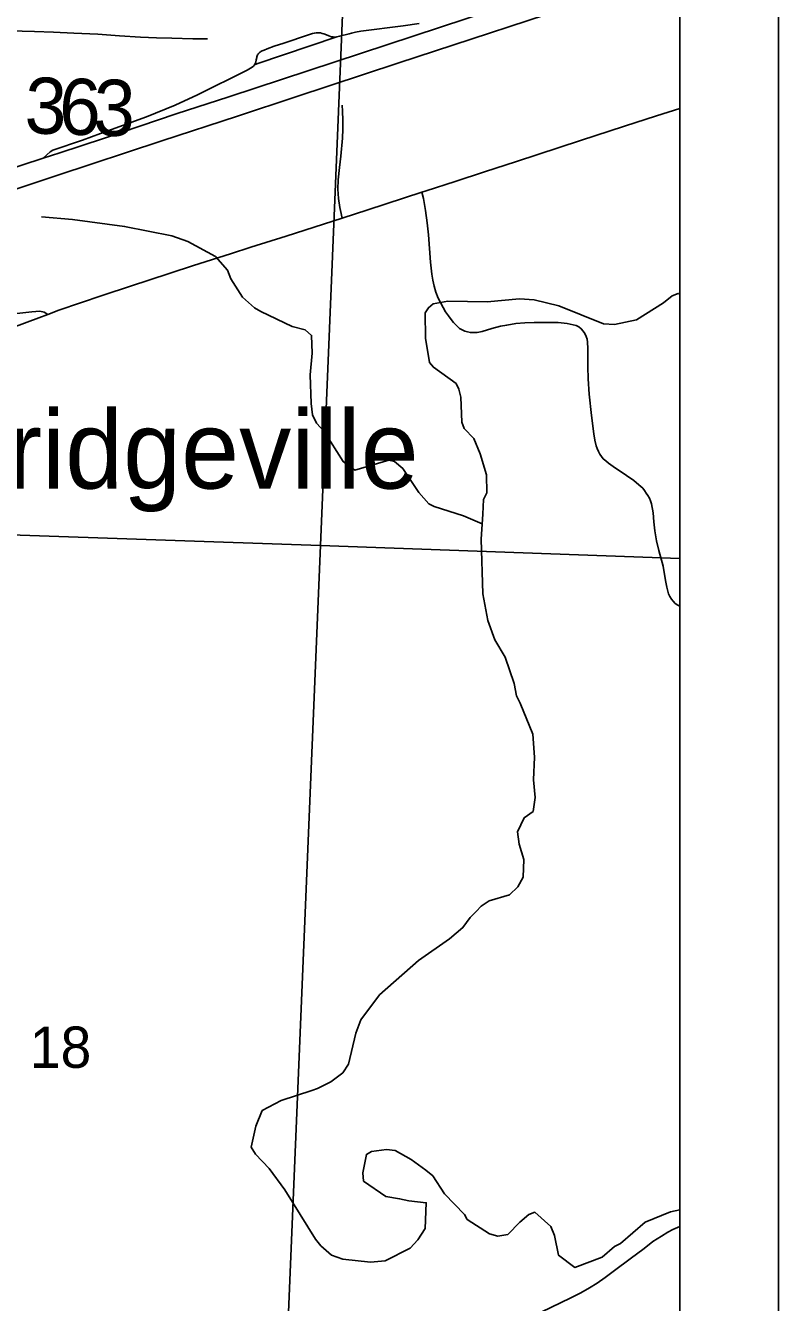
# Model space of a CAD drawing. Extents: x 0 to 34, y 0 to 22.
# Drawn here: x 8.237 to 9, y 16.42 to 17.712 of the extents above; entities that cross this region are included whole.
import ezdxf

# ---------------------------------------------------------------- set-up
doc = ezdxf.new("R2010")
doc.units = 0
for name, color, linetype in [('GM_X_Interchange_Ramps', 7, 'Continuous'), ('GM_X_Interstate_Route', 7, 'Continuous'), ('GM_X_Minor_River', 7, 'Continuous'), ('GM_X_Rail_Line', 7, 'Continuous'), ('GM_X_Section', 7, 'Continuous'), ('GM_X_Section_Text', 7, 'Continuous'), ('GM_X_Township_Road', 7, 'Continuous'), ('GM_X_Township_Road_Text', 7, 'Continuous'), ('GM_X_Unincorporated_Text', 7, 'Continuous'), ('GM_X_US_Route', 7, 'Continuous'), ('SH_Data', 7, 'Continuous')]:
    doc.layers.add(name, color=color, linetype=linetype)

msp = doc.modelspace()

# ---------------------------------------------------------------- linework, layer by layer
at = {"layer": 'GM_X_Interchange_Ramps'}
for points in [[(8.6362, 17.7146), (8.62, 17.7122), (8.5769, 17.7067), (8.5714, 17.7057), (8.5676, 17.7048), (8.5651, 17.7041), (8.5555, 17.7015), (8.5525, 17.7009), (8.5494, 17.7008), (8.5485, 17.7009), (8.5474, 17.701), (8.5464, 17.7013), (8.5447, 17.702), (8.5423, 17.703), (8.5395, 17.704), (8.5379, 17.7045), (8.5362, 17.7049), (8.5347, 17.7051), (8.5338, 17.7052), (8.533, 17.7052), (8.5316, 17.705), (8.5298, 17.7046), (8.5279, 17.7042), (8.5241, 17.7031), (8.499, 17.6946), (8.4891, 17.6914), (8.482, 17.6888), (8.479, 17.6876), (8.4771, 17.6868), (8.4756, 17.686), (8.475, 17.6856), (8.4744, 17.6852), (8.4739, 17.6848), (8.4733, 17.6842), (8.4728, 17.6835), (8.4723, 17.6826), (8.472, 17.6819), (8.4717, 17.6809), (8.4715, 17.6799), (8.4711, 17.6777), (8.4706, 17.6754), (8.47, 17.6739), (8.4692, 17.6726), (8.4681, 17.6714), (8.467, 17.6704), (8.4653, 17.6693), (8.4617, 17.6671), (8.4115, 17.6423), (8.3888, 17.6318), (8.36, 17.6201), (8.3131, 17.603), (8.2949, 17.5965), (8.265, 17.5861), (8.2623, 17.5845), (8.2553, 17.5781)], [(8.5525, 17.7009), (8.4716, 17.6738), (8.4692, 17.6726)]]:
    msp.add_lwpolyline(points, dxfattribs=at)
at = {"layer": 'GM_X_Interstate_Route'}
for points in [[(8.1512, 17.5213), (8.2691, 17.5606), (8.3753, 17.5956), (8.4521, 17.6208), (8.5111, 17.6402), (8.6143, 17.6743), (8.8209, 17.742)], [(7.2772, 17.4256), (7.4507, 17.4388), (7.6458, 17.4538), (7.7914, 17.465), (7.8502, 17.4696), (7.8812, 17.4725), (7.9059, 17.4755), (7.9274, 17.4788), (7.9488, 17.4827), (7.9701, 17.4873), (7.9912, 17.4927), (8.0152, 17.4996), (8.0507, 17.5108), (8.0653, 17.5156), (8.213, 17.5644), (8.2553, 17.5781), (8.2721, 17.5836), (8.3164, 17.5982), (8.39, 17.6229), (8.4432, 17.6401), (8.711, 17.7284)]]:
    msp.add_lwpolyline(points, dxfattribs=at)
at = {"layer": 'GM_X_Minor_River'}
for points in [[(8.6999, 17.2078), (8.6809, 17.216), (8.6513, 17.2253), (8.646, 17.2283), (8.6357, 17.2397), (8.6196, 17.2638), (8.6109, 17.271), (8.6052, 17.2725), (8.5708, 17.2624), (8.559, 17.271), (8.5398, 17.3013), (8.5322, 17.3099), (8.528, 17.3183), (8.5268, 17.3296), (8.5258, 17.3588), (8.5276, 17.3808), (8.5271, 17.3987), (8.5206, 17.4043), (8.5073, 17.4076), (8.4758, 17.423), (8.4693, 17.4267), (8.4571, 17.4373), (8.4453, 17.4558), (8.4418, 17.4649), (8.4296, 17.4785), (8.4018, 17.4938), (8.3855, 17.4994), (8.3377, 17.509), (8.285, 17.5159), (8.2536, 17.5187)], [(8.9, 17.4403), (8.8984, 17.4412), (8.8923, 17.4389), (8.8837, 17.4316), (8.8561, 17.4144), (8.8338, 17.4097), (8.8228, 17.4104), (8.7776, 17.4287), (8.7526, 17.4346), (8.7378, 17.4356), (8.7049, 17.4328), (8.6651, 17.4333), (8.6503, 17.4305), (8.6454, 17.4267), (8.6421, 17.4214), (8.6426, 17.396), (8.6466, 17.3713), (8.6504, 17.3664), (8.6736, 17.3499), (8.6763, 17.3442), (8.6782, 17.3363), (8.6792, 17.3109), (8.6815, 17.3044), (8.6914, 17.2942), (8.6979, 17.2787), (8.7041, 17.2575), (8.7046, 17.2393), (8.7013, 17.2325), (8.7006, 17.2177), (8.6989, 17.1923), (8.7004, 17.1369), (8.7055, 17.11), (8.7128, 17.0903), (8.7232, 17.0729), (8.7324, 17.0464), (8.7348, 17.0339), (8.7383, 17.0264)], [(8.7383, 17.0264), (8.7513, 16.995), (8.753, 16.9718), (8.752, 16.9487), (8.7537, 16.9309), (8.7515, 16.9168), (8.7424, 16.9103), (8.7357, 16.8962), (8.7373, 16.8837), (8.742, 16.8682), (8.7413, 16.85), (8.7361, 16.8405), (8.7274, 16.8324), (8.707, 16.8263), (8.6987, 16.8209), (8.6938, 16.8155), (8.6878, 16.8094), (8.6803, 16.7992), (8.6667, 16.7877), (8.6355, 16.7659), (8.5959, 16.7311), (8.5768, 16.7056), (8.5719, 16.6923), (8.5646, 16.6607), (8.5586, 16.652), (8.5465, 16.6428), (8.5329, 16.6362), (8.5272, 16.6343), (8.4963, 16.6239), (8.477, 16.6139), (8.4707, 16.5979), (8.4659, 16.5767), (8.4701, 16.5698), (8.4842, 16.5551), (8.4999, 16.5336), (8.5309, 16.4837), (8.5363, 16.4769), (8.5473, 16.4675), (8.5587, 16.4634), (8.5867, 16.4602), (8.6015, 16.4618), (8.6268, 16.4745), (8.6347, 16.4829), (8.6422, 16.4943), (8.6432, 16.5205), (8.6257, 16.5226), (8.6162, 16.5245), (8.6022, 16.527), (8.5798, 16.5425), (8.5789, 16.5508), (8.5826, 16.5694), (8.5879, 16.5725), (8.603, 16.5745), (8.6117, 16.5734), (8.6281, 16.5644), (8.6429, 16.5535), (8.6498, 16.5478), (8.6617, 16.5297), (8.6819, 16.5086), (8.6846, 16.5037), (8.7074, 16.489), (8.7157, 16.4868), (8.7259, 16.4884), (8.738, 16.501), (8.747, 16.5086), (8.7531, 16.5109), (8.7694, 16.4966), (8.7733, 16.4872), (8.7772, 16.4674), (8.7936, 16.455), (8.8215, 16.4654), (8.834, 16.4761), (8.84, 16.4792), (8.8649, 16.501), (8.8905, 16.5114), (8.9, 16.5133)]]:
    msp.add_lwpolyline(points, dxfattribs=at)
at = {"layer": 'GM_X_Rail_Line'}
msp.add_lwpolyline([(6.4764, 15.22), (8.4272, 15.1429), (8.9, 15.1329), (8.9, 20.2439), (7.9141, 20.2806), (7.3096, 20.3035), (6.6357, 20.3306)], dxfattribs=at)
at = {"layer": 'GM_X_Section'}
for points in [[(7.5782, 18.246), (8.5787, 18.2117), (8.5361, 17.186), (8.0548, 17.2024), (8.0736, 17.7137), (7.5651, 17.7332)], [(8.0548, 17.2024), (8.5361, 17.186), (8.4938, 16.1751), (8.0113, 16.1881)]]:
    msp.add_lwpolyline(points, close=True, dxfattribs=at)
at = {"layer": 'GM_X_Township_Road'}
for points in [[(8.0762, 17.7113), (8.0799, 17.7118), (8.0848, 17.712), (8.0988, 17.7118), (8.1212, 17.7112), (8.1425, 17.7105), (8.1658, 17.7095), (8.1841, 17.7087), (8.1969, 17.708), (8.2154, 17.7073), (8.234, 17.7067), (8.2463, 17.7063), (8.2658, 17.7057), (8.2864, 17.7047), (8.3106, 17.7036), (8.3324, 17.7021), (8.3538, 17.7008), (8.3699, 17.7001), (8.3856, 17.6998), (8.4067, 17.6991), (8.4217, 17.6989)], [(8.5582, 17.5175), (8.5565, 17.5252), (8.5558, 17.5282), (8.5545, 17.5373), (8.5537, 17.5468), (8.5541, 17.5563), (8.5553, 17.5687), (8.5567, 17.5801), (8.5583, 17.5984), (8.5586, 17.6075), (8.5588, 17.6167), (8.5583, 17.6258), (8.558, 17.6319)], [(8.9, 17.1245), (8.898, 17.1256), (8.8955, 17.1273), (8.8932, 17.1295), (8.8915, 17.1317), (8.8901, 17.1343), (8.8887, 17.1371), (8.887, 17.1437), (8.8857, 17.1505), (8.8832, 17.1652), (8.8788, 17.181), (8.8765, 17.1908), (8.8749, 17.2008), (8.8738, 17.2099), (8.8731, 17.2192), (8.8715, 17.2283), (8.8705, 17.2311), (8.8692, 17.2339), (8.8677, 17.2366), (8.866, 17.2391), (8.8644, 17.2415), (8.8625, 17.2439), (8.8585, 17.2475), (8.8536, 17.2518), (8.8461, 17.2569), (8.8324, 17.266), (8.8278, 17.2694), (8.825, 17.2717), (8.8225, 17.2738), (8.8208, 17.276), (8.8191, 17.2785), (8.8176, 17.2813), (8.8163, 17.2841), (8.8152, 17.287), (8.8139, 17.2926), (8.8131, 17.299), (8.8106, 17.3175), (8.8084, 17.3392), (8.8074, 17.3546), (8.8068, 17.367), (8.8068, 17.3855), (8.8066, 17.3917), (8.8061, 17.3948), (8.8053, 17.3977), (8.804, 17.4005), (8.8023, 17.4031), (8.8002, 17.4054), (8.7978, 17.4073), (8.795, 17.4086), (8.792, 17.4094), (8.786, 17.4107), (8.78, 17.4115), (8.777, 17.4117), (8.7739, 17.4117), (8.7678, 17.4117), (8.7524, 17.4118), (8.7431, 17.4115), (8.7338, 17.4107), (8.7247, 17.4092), (8.7186, 17.408), (8.7096, 17.4056), (8.7, 17.4028), (8.6947, 17.4017), (8.6912, 17.4016), (8.688, 17.4016), (8.6851, 17.4023), (8.6824, 17.403), (8.6796, 17.4044), (8.6769, 17.4058), (8.6743, 17.4083), (8.6709, 17.4117), (8.6684, 17.4147), (8.6656, 17.4184), (8.6627, 17.4227), (8.6602, 17.4268), (8.6554, 17.4364), (8.6531, 17.4424), (8.6514, 17.4486), (8.6499, 17.4546), (8.6488, 17.4607), (8.6475, 17.473), (8.6454, 17.5006), (8.6442, 17.5128), (8.6426, 17.5251), (8.6416, 17.5312), (8.6403, 17.5372), (8.6388, 17.5438)], [(8.26, 17.4199), (8.2711, 17.4241), (8.3151, 17.4391), (8.3447, 17.4488), (8.3623, 17.4546), (8.4066, 17.4691), (8.4332, 17.4776), (8.445, 17.4814), (8.4657, 17.488), (8.5013, 17.4991), (8.5582, 17.5175)], [(8.0562, 17.4067), (8.0682, 17.4089), (8.0866, 17.4112), (8.1023, 17.4127), (8.1271, 17.4142), (8.1488, 17.4153), (8.1643, 17.4161), (8.183, 17.4172), (8.2136, 17.4193), (8.2437, 17.4225), (8.2517, 17.4232), (8.2562, 17.4221), (8.26, 17.4199)], [(8.6196, 16.3476), (8.633, 16.3537), (8.646, 16.3592), (8.6793, 16.3739), (8.6933, 16.38), (8.7053, 16.3852), (8.7263, 16.3944), (8.7443, 16.4028), (8.7603, 16.4102), (8.7891, 16.424), (8.7999, 16.4292), (8.8087, 16.4343), (8.8165, 16.4391), (8.8246, 16.445), (8.8338, 16.4518), (8.8498, 16.4637), (8.864, 16.4742), (8.8729, 16.4813), (8.8814, 16.4868), (8.8879, 16.4908), (8.8929, 16.4933), (8.8977, 16.4956), (8.9, 16.4965)]]:
    msp.add_lwpolyline(points, dxfattribs=at)
at = {"layer": 'GM_X_Unincorporated_Text'}
for points in [[(8.9, 17.1728), (8.9, 18.1906), (8.5787, 18.2117), (8.5361, 17.186)], [(8.9, 16.1585), (8.9, 17.1728), (8.5361, 17.186), (8.4938, 16.1751)]]:
    msp.add_lwpolyline(points, close=True, dxfattribs=at)
at = {"layer": 'GM_X_US_Route'}
for points in [[(8.6388, 17.5438), (8.643, 17.5451), (8.6726, 17.5546), (8.7021, 17.5642), (8.7347, 17.5747), (8.7996, 17.5959), (8.8439, 17.6104), (8.8765, 17.6209), (8.9, 17.6285)], [(8.5582, 17.5175), (8.584, 17.5259), (8.6388, 17.5438)], [(8.26, 17.4199), (8.2711, 17.4241), (8.3151, 17.4391), (8.3447, 17.4488), (8.3623, 17.4546), (8.4066, 17.4691), (8.4332, 17.4776), (8.445, 17.4814), (8.4657, 17.488), (8.5013, 17.4991), (8.5582, 17.5175)], [(8.0166, 17.3242), (8.034, 17.331), (8.0889, 17.3527), (8.1206, 17.3655), (8.1581, 17.3805), (8.1871, 17.3916), (8.2073, 17.3998), (8.2246, 17.4066), (8.2507, 17.4165), (8.26, 17.4199)]]:
    msp.add_lwpolyline(points, dxfattribs=at)
at = {"layer": 'SH_Data'}
for p, q in [((9, 21), (9, 14)), ((8.9, 20.9), (8.9, 14.1))]:
    msp.add_line(p, q, dxfattribs=at)

# ---------------------------------------------------------------- texts
at = {"layer": 'GM_X_Section_Text'}
msp.add_text('18', height=0.04186, rotation=0, dxfattribs=at).set_placement((8.2417, 16.6571))
at = {"layer": 'GM_X_Township_Road_Text'}
for s, rotation, p in [('3', 358.2416, (8.2359, 17.6035)), ('6', 358.2451, (8.2706, 17.6024)), ('3', 358.2567, (8.3053, 17.6014))]:
    msp.add_text(s, height=0.0568, rotation=rotation, dxfattribs=at).set_placement(p)
at = {"layer": 'GM_X_Unincorporated_Text'}
msp.add_text('Bridgeville', height=0.078977, rotation=0, dxfattribs=at).set_placement((8.1484, 17.2436))

doc.saveas('drawing.dxf')
